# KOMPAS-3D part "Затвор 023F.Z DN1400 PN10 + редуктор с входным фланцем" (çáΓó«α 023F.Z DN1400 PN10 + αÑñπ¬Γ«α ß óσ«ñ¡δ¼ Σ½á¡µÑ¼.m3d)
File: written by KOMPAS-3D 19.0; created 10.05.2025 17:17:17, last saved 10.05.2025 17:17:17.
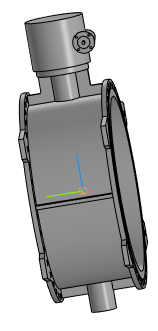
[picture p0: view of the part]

Document properties: Полное имя файла: Затвор 023F.Z DN1400 PN10 + редуктор с входным фланцем.a3d

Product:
- Part/product: Затвор 023F.Z DN1400 PN10 + редуктор с входным фланцем
    Масса: 3312.36

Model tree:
1. Операция без истории:1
